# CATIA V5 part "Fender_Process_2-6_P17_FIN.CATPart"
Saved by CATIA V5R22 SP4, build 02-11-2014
Part number: Fender
Bounding box of the stored display mesh (mm): x 0 to 0, y 0 to 107.117, z 0 to 450
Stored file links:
  C:\DATA\Car_ASSY\教育モデル\2_SKE\Fender_Process_2-6_P17_FIN.CATPart
  C:\DATA\Car_ASSY\教育モデル\3_SOL\Car_Fender.CATPart
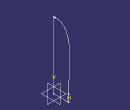
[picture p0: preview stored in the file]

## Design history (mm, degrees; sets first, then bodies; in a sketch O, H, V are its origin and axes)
Body1 (main body)
Body2
  Sketch1 on yz-plane, origin (0, 0, 0), H (0, 1, 0), V (0, 0, 1)
    point P4 (100, 50)
    point P5 (10, 450)
    spline S1 through (10, 450) (100, 50)
    line L1 (0, 450) -> (10, 450)
    line L2 (0, 0) -> (0, 450)
    line L3 (100, 0) -> (0, 0)
    line L4 (100, 50) -> (100, 0)
    point P6 (100, 50)
    point P7 (10, 450)
    distance P4 L3 = 50
    distance P5 L2 = 10
    distance L4 L2 = 100
    distance L1 H = 450
    coincidence: L2 V, H L3, P4 P6, P7 P5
